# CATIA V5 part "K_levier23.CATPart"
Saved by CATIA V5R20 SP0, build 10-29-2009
Part number: levier 23
Publications: "demi largeur balancier", "epaisseur pieces", "Plan.-30", "liaison 57/23", "liaison 10/23 sur 23"
Bounding box of the stored display mesh (mm): x -60 to -30, y -1014.999 to -695.001, z 335.016 to 749.984
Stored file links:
  G:\Khaled_CFAO_2011\SIL\SIL_GR2\mdardier\Khaled\CAD_ThinkMOTION\K_levier23.CATPart
  G:\Khaled_CFAO_2011\SIL\SIL_GR2\mdardier\Khaled\CAD_ThinkMOTION\K_ass_tandem.CATProduct
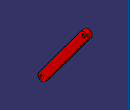
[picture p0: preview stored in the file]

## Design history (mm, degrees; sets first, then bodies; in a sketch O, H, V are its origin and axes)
External parameters (linked from other documents)
  `External.demi largeur balancier` = 50 mm
  `External.epaisseur pieces` = 30 mm
Set1
  Plane1 "Plan.-30": linked copy from another document
  Point1 "liaison 57/23": linked copy from another document
  Point2 "liaison 10/23 sur 23": linked copy from another document
Body1 (main body)
  Sketch1 on Plane1, origin (-30, 0, 0), H (0, 1, 0), V (0, 0, 1)
    construction line L1 (-720, 725) -> (-990, 360)
    point P1 (-720, 725)
    point P2 (-990, 360)
    line L2 (-699.9013, 710.1325) -> (-969.9013, 345.1325)
    line L3 (-1010.0987, 374.8675) -> (-740.0987, 739.8675)
    arc A1 centre (-990, 360) radius 25 from (-969.9013, 345.1325) to (-1010.0987, 374.8675) cw
    arc A2 centre (-720, 725) radius 25 from (-740.0987, 739.8675) to (-699.9013, 710.1325) cw
    reference projected point E1 (-720, 725) from Point1
    reference projected point E2 (-990, 360) from Point2
    circle A3 centre (-990, 360) radius 12.5
    point P7 (-990, 360)
    reference projected point E3 (-990, 360) from Point2
    circle A4 centre (-720, 725) radius 10
    point P8 (-720, 725)
    reference projected point E4 (-720, 725) from Point1
    distance L1 L2 = 25 {= `External.demi largeur balancier` /2}
    radius A3 = 12.5 {= `External.demi largeur balancier` /4}
    radius A4 = 10 {= `External.demi largeur balancier` /5}
    tangency: A1 L2, A2 L2, A1 L3, A2 L3
    coincidence: P1 E1, P2 E2, P7 E3, P8 E4
  Pad1: profile Sketch1, direction (-1, 0, 0), length 30 {= `External.epaisseur pieces`}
